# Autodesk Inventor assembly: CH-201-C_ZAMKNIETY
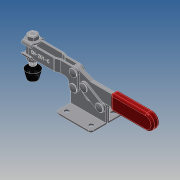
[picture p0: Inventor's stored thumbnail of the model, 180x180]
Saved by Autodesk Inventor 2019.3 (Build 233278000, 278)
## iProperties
Company: ·L?¤¤?
Created: 2010-06
Part Number: CH-201-C_ZAMKNIETY
Material: Ogólny
Description: STEP AP203
Document SubType Name: Assembly
Designer: CADENGINEERING4
Sending System: SolidWorks 2005179
Preprocessor: SwSTEP 2.0
Title: CH-201-C.STEP
Author: ·L?¥Î?
Revision Number: ANY
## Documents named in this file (10)
- E:\STRONA\Horizontal toggle clamp\CH-201-C\CH-201-C_ZAMKNIETY.iam
- E:\STRONA\Horizontal toggle clamp\CH-201-C\201-C-02___.ipt
- E:\STRONA\Horizontal toggle clamp\CH-201-C\201-C-06___.ipt
- E:\STRONA\Horizontal toggle clamp\CH-201-C\201-C-03___.ipt
- E:\STRONA\Horizontal toggle clamp\CH-201-C\14134-01___.ipt
- E:\STRONA\Horizontal toggle clamp\CH-201-C\201-C-04___.ipt
- E:\STRONA\Horizontal toggle clamp\CH-201-C\201-C-05___.ipt
- E:\STRONA\Horizontal toggle clamp\CH-201-C\FW140___.ipt
- E:\STRONA\Horizontal toggle clamp\CH-201-C\201-C-01___.ipt
- E:\STRONA\Horizontal toggle clamp\CH-201-C\14134___.ipt
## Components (15 placed, 15 different names)
1. 201-C-02_??_1 — Równoległe:1, Zestawiające:10, Zestawiające:11, Zestawiające:12, Zestawiające:23, Zestawiające:24, Zestawiające:25, Zestawiające:28, Zestawiające:30
2. 201-C-06_??_2 — Zestawiające:22, Zestawiające:23, Zestawiające:25
3. 201-C-03_??_3 — Zestawiające:1, Zestawiające:2, Zestawiające:3, Zestawiające:26, Zestawiające:27, Zestawiające:29, Przejściowe:1
4. 14134-01_??_4 — Równoległe:3, Zestawiające:5, Zestawiające:9
5. 201-C-04_??_5 — Zestawiające:13, Zestawiające:16, Zestawiające:17
6. 201-C-05_??_6 — Zestawiające:1, Zestawiające:2, Zestawiające:3
7. 201-C-06_??_7 — Zestawiające:28, Zestawiające:29, Zestawiające:30
8. FW140_??_8 — Równoległe:1, Równoległe:2, Zestawiające:6, Zestawiające:9, Zestawiające:10
9. FW140_??_9 — Równoległe:2, Zestawiające:4, Zestawiające:8, Zestawiające:11
10. 201-C-06_??_10 — Zestawiające:20, Zestawiające:21, Zestawiające:27
11. 201-C-01_??_11 — Zestawiające:13, Zestawiające:14, Zestawiające:15, Zestawiające:16, Zestawiające:22, Zestawiające:24, Przejściowe:1
12. 201-C-06_??_12 — Zestawiające:18, Zestawiające:19
13. 201-C-04_??_13 — Zestawiające:14, Zestawiające:15, Zestawiające:17, Zestawiające:18, Zestawiające:19, Zestawiające:20, Zestawiające:21, Zestawiające:26
14. 14134-01_??_14 — Zestawiające:7, Zestawiające:8
15. 14134_??_15 — Równoległe:3, Zestawiające:4, Zestawiające:5, Zestawiające:6, Zestawiające:7, Zestawiające:12
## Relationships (34: Mate 30, Flush 3, Transitional 1)
- Równoległe:1 [Flush]: 201-C-02_??_1 ↔ FW140_??_8
- Równoległe:2 [Flush]: FW140_??_8 ↔ FW140_??_9
- Równoległe:3 [Flush]: 14134-01_??_4 ↔ 14134_??_15
- Zestawiające:1 [Mate]: 201-C-03_??_3 ↔ 201-C-05_??_6
- Zestawiające:2 [Mate]: 201-C-03_??_3 ↔ 201-C-05_??_6
- Zestawiające:3 [Mate]: 201-C-03_??_3 ↔ 201-C-05_??_6
- Zestawiające:4 [Mate]: FW140_??_9 ↔ 14134_??_15
- Zestawiające:5 [Mate]: 14134-01_??_4 ↔ 14134_??_15
- Zestawiające:6 [Mate]: FW140_??_8 ↔ 14134_??_15
- Zestawiające:7 [Mate]: 14134-01_??_14 ↔ 14134_??_15
- Zestawiające:8 [Mate]: FW140_??_9 ↔ 14134-01_??_14
- Zestawiające:9 [Mate]: 14134-01_??_4 ↔ FW140_??_8
- Zestawiające:10 [Mate]: 201-C-02_??_1 ↔ FW140_??_8
- Zestawiające:11 [Mate]: 201-C-02_??_1 ↔ FW140_??_9
- Zestawiające:12 [Mate]: 201-C-02_??_1 ↔ 14134_??_15
- Zestawiające:13 [Mate]: 201-C-04_??_5 ↔ 201-C-01_??_11
- Zestawiające:14 [Mate]: 201-C-01_??_11 ↔ 201-C-04_??_13
- Zestawiające:15 [Mate]: 201-C-01_??_11 ↔ 201-C-04_??_13
- Zestawiające:16 [Mate]: 201-C-04_??_5 ↔ 201-C-01_??_11
- Zestawiające:17 [Mate]: 201-C-04_??_5 ↔ 201-C-04_??_13
- Zestawiające:18 [Mate]: 201-C-06_??_12 ↔ 201-C-04_??_13
- Zestawiające:19 [Mate]: 201-C-06_??_12 ↔ 201-C-04_??_13
- Zestawiające:20 [Mate]: 201-C-06_??_10 ↔ 201-C-04_??_13
- Zestawiające:21 [Mate]: 201-C-06_??_10 ↔ 201-C-04_??_13
- Zestawiające:22 [Mate]: 201-C-06_??_2 ↔ 201-C-01_??_11
- Zestawiające:23 [Mate]: 201-C-02_??_1 ↔ 201-C-06_??_2
- Zestawiające:24 [Mate]: 201-C-02_??_1 ↔ 201-C-01_??_11
- Zestawiające:25 [Mate]: 201-C-02_??_1 ↔ 201-C-06_??_2
- Zestawiające:26 [Mate]: 201-C-03_??_3 ↔ 201-C-04_??_13
- Zestawiające:27 [Mate]: 201-C-03_??_3 ↔ 201-C-06_??_10
- Zestawiające:28 [Mate]: 201-C-02_??_1 ↔ 201-C-06_??_7
- Zestawiające:29 [Mate]: 201-C-03_??_3 ↔ 201-C-06_??_7
- Zestawiające:30 [Mate]: 201-C-02_??_1 ↔ 201-C-06_??_7
- Przejściowe:1 [Transitional]: 201-C-03_??_3 ↔ 201-C-01_??_11
